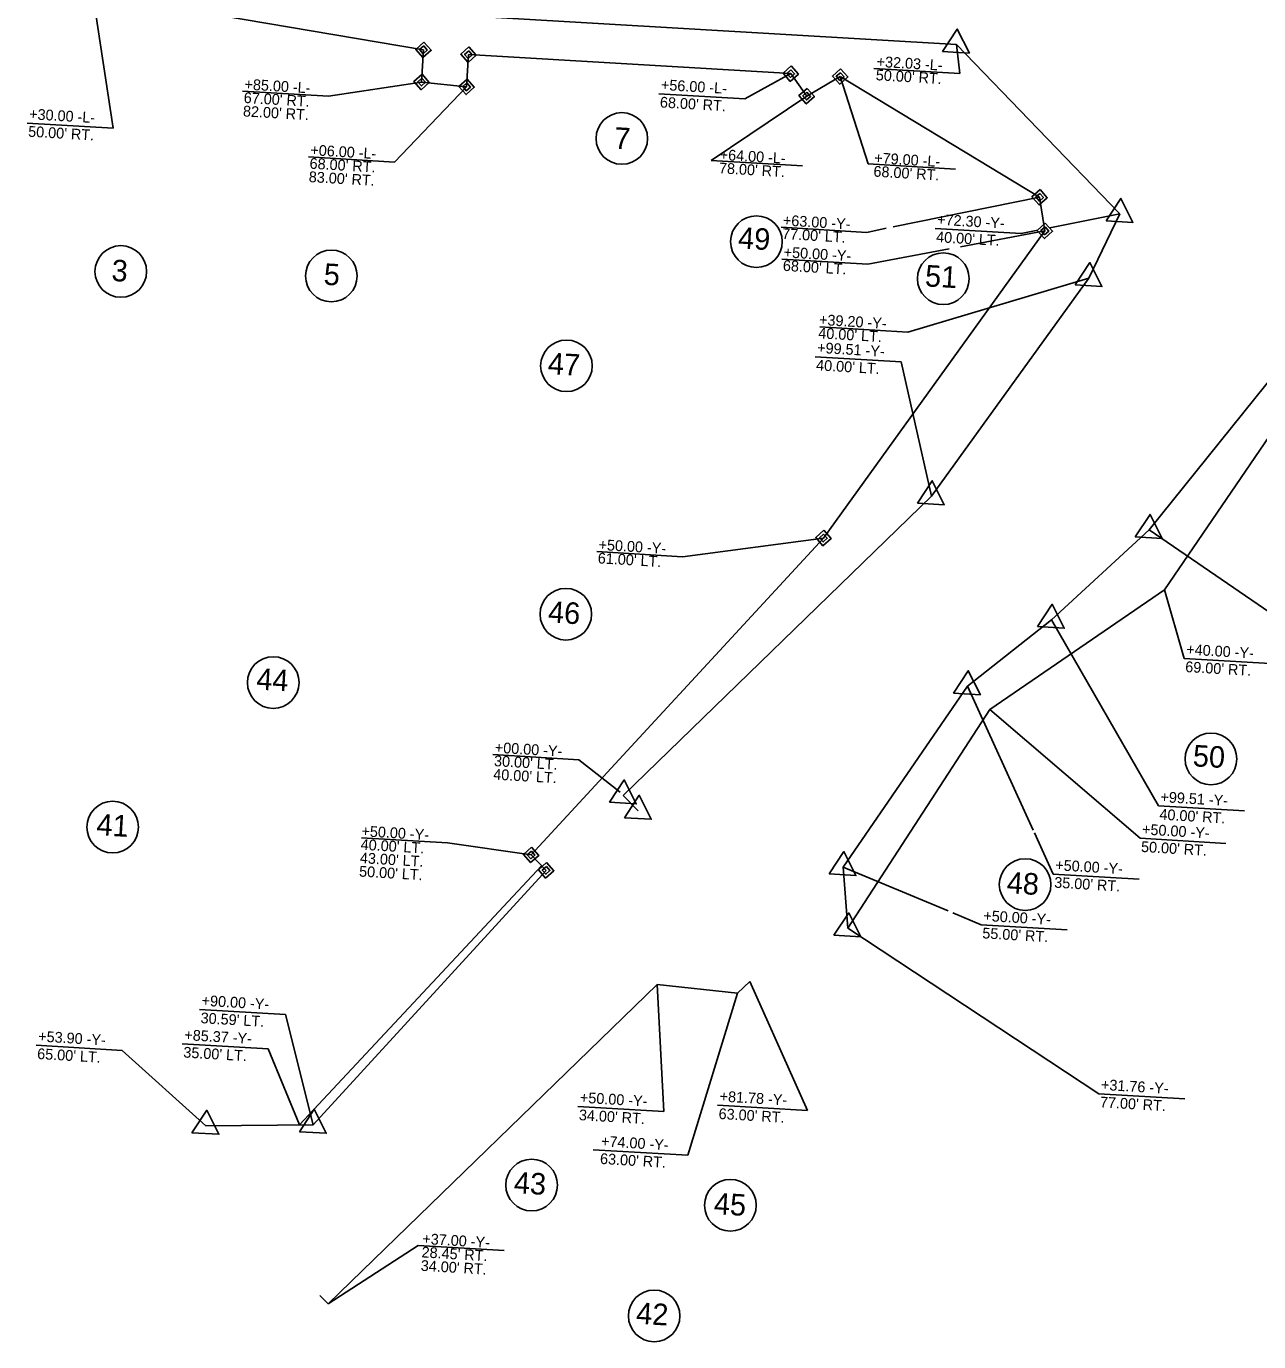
# Model space of a CAD drawing. Extents: x 2010883 to 2014849, y 442000 to 447413.
# Drawn here: x 2011335 to 2011908, y 444349 to 444960 of the extents above; entities that cross this region are included whole.
import ezdxf

# ---------------------------------------------------------------- set-up
doc = ezdxf.new("R2010")
doc.units = 0
for name, color, linetype in [('Prop Easement Construction', 7, 'Continuous'), ('Prop Easement Construction Station Offsets', 7, 'Continuous'), ('Prop Easement Permanent Utility', 7, 'Continuous'), ('Prop Easement Permanent Utility Station Offsets', 7, 'Continuous'), ('Prop Parcel Number CELL', 7, 'Continuous'), ('Prop Parcel Number Text', 7, 'Continuous'), ('Prop ROW Marker CELL', 7, 'Continuous'), ('Prop ROW Permanent Easement CELL', 7, 'Continuous'), ('Prop ROW RW Lines', 7, 'Continuous'), ('Prop ROW Station Offsets', 7, 'Continuous')]:
    doc.layers.add(name, color=color, linetype=linetype)

msp = doc.modelspace()

# ---------------------------------------------------------------- linework, layer by layer
at = {"layer": 'Prop Easement Construction'}
for p, q in [((2011864.2, 444698.09), (2011941.73, 444811.57)), ((2011783.13, 444642.47), (2011864.2, 444698.09)), ((2011717.13, 444540.72), (2011783.13, 444642.47)), ((2011462.36, 444449.38), (2011574.87, 444569.83)), ((2011475.74, 444366.18), (2011628.53, 444514.6)), ((2011628.53, 444514.6), (2011665.95, 444510.52)), ((2011665.95, 444510.52), (2011671.53, 444515.94)), ((2011471.88, 444370.16), (2011475.74, 444366.18))]:
    msp.add_line(p, q, dxfattribs=at)
at = {"layer": 'Prop Easement Construction Station Offsets'}
for p, q in [((2011864.2, 444698.09), (2011873.43, 444666.16)), ((2011873.43, 444666.16), (2011913.36, 444663.81)), ((2011783.13, 444642.47), (2011852.89, 444582.57)), ((2011852.89, 444582.57), (2011892.82, 444580.21)), ((2011628.53, 444514.6), (2011631.66, 444455.57)), ((2011671.53, 444515.94), (2011698.34, 444456.03)), ((2011665.95, 444510.52), (2011642.78, 444435.25)), ((2011407.95, 444487.02), (2011447.88, 444484.67)), ((2011462.36, 444449.38), (2011447.88, 444484.67)), ((2011591.73, 444457.92), (2011631.66, 444455.57)), ((2011656.64, 444458.49), (2011698.34, 444456.03)), ((2011598.86, 444437.84), (2011642.78, 444435.25)), ((2011475.74, 444366.18), (2011517.47, 444393.31)), ((2011517.47, 444393.31), (2011557.4, 444390.95))]:
    msp.add_line(p, q, dxfattribs=at)
at = {"layer": 'Prop Easement Permanent Utility'}
for p, q in [((2011366.24, 444975.07), (2011519.97, 444948.98)), ((2011519.97, 444948.98), (2011519.09, 444934)), ((2011540, 444931.77), (2011540.88, 444946.74)), ((2011540.88, 444946.74), (2011690.62, 444937.92)), ((2011690.62, 444937.92), (2011698.02, 444927.46)), ((2011698.02, 444927.46), (2011713.58, 444936.56)), ((2011713.58, 444936.56), (2011806.21, 444880.48)), ((2011519.09, 444934), (2011540, 444931.77)), ((2011808.65, 444864.86), (2011806.21, 444880.48)), ((2011705.79, 444722.09), (2011808.65, 444864.86)), ((2011570, 444574.85), (2011705.79, 444722.09)), ((2011570, 444574.85), (2011576.96, 444567.67)), ((2011468.76, 444449.44), (2011576.96, 444567.67))]:
    msp.add_line(p, q, dxfattribs=at)
at = {"layer": 'Prop Easement Permanent Utility Station Offsets'}
for p, q in [((2011366.24, 444975.07), (2011375.79, 444912.6)), ((2011690.62, 444937.92), (2011669.3, 444926.19)), ((2011713.58, 444936.56), (2011726.53, 444895.97)), ((2011519.09, 444934), (2011475.89, 444927.37)), ((2011540, 444931.77), (2011506.48, 444896.84)), ((2011435.96, 444929.73), (2011475.89, 444927.37)), ((2011629.37, 444928.54), (2011669.3, 444926.19)), ((2011698.02, 444927.46), (2011653.65, 444897.55)), ((2011335.86, 444914.96), (2011375.79, 444912.6)), ((2011466.55, 444899.19), (2011506.48, 444896.84)), ((2011653.65, 444897.55), (2011696.14, 444895.05)), ((2011726.53, 444895.97), (2011767.15, 444893.57)), ((2011806.21, 444880.48), (2011738.26, 444866.77)), ((2011686.09, 444866.51), (2011726.02, 444864.16)), ((2011734.89, 444866.05), (2011726.02, 444864.16)), ((2011808.65, 444864.86), (2011769.47, 444857.48)), ((2011686.45, 444851.71), (2011726.38, 444849.35)), ((2011764.25, 444856.49), (2011726.38, 444849.35)), ((2011705.79, 444722.09), (2011640.38, 444713.41)), ((2011600.45, 444715.77), (2011640.38, 444713.41)), ((2011491.25, 444582.75), (2011531.18, 444580.4)), ((2011570, 444574.85), (2011531.18, 444580.4))]:
    msp.add_line(p, q, dxfattribs=at)
at = {"layer": 'Prop Parcel Number CELL'}
for p, q in [((2011612.14, 444907.78), (2011612.14, 444907.78)), ((2011674.67, 444859.84), (2011674.67, 444859.84)), ((2011379.37, 444845.97), (2011379.37, 444845.97)), ((2011477.17, 444843.89), (2011477.17, 444843.89)), ((2011761.49, 444842.61), (2011761.49, 444842.61)), ((2011586.42, 444802.12), (2011586.42, 444802.12)), ((2011586.12, 444686.71), (2011586.12, 444686.71)), ((2011450.18, 444654.94), (2011450.18, 444654.94)), ((2011885.84, 444619.45), (2011885.84, 444619.45)), ((2011375.58, 444587.76), (2011375.58, 444587.76)), ((2011799.52, 444561.06), (2011799.52, 444561.06)), ((2011570.23, 444421.41), (2011570.23, 444421.41)), ((2011662.57, 444412.03), (2011662.57, 444412.03)), ((2011627.16, 444360.62), (2011627.16, 444360.62))]:
    msp.add_line(p, q, dxfattribs=at)
for centre in [(2011612.14, 444907.78), (2011674.67, 444859.84), (2011379.37, 444845.97), (2011477.17, 444843.89), (2011761.49, 444842.61), (2011586.42, 444802.12), (2011586.12, 444686.71), (2011450.18, 444654.94), (2011885.84, 444619.45), (2011375.58, 444587.76), (2011799.52, 444561.06), (2011570.23, 444421.41), (2011662.57, 444412.03), (2011627.16, 444360.62)]:
    msp.add_circle(centre, 12, dxfattribs=at)
at = {"layer": 'Prop ROW Marker CELL'}
for p, q in [((2011519.97, 444948.98), (2011519.97, 444948.98)), ((2011767.58, 444951.41), (2011767.58, 444951.41)), ((2011540.88, 444946.74), (2011540.88, 444946.74)), ((2011690.62, 444937.92), (2011690.62, 444937.92)), ((2011713.58, 444936.56), (2011713.58, 444936.56)), ((2011519.09, 444934), (2011519.09, 444934)), ((2011540, 444931.77), (2011540, 444931.77)), ((2011698.02, 444927.46), (2011698.02, 444927.46)), ((2011806.21, 444880.48), (2011806.21, 444880.48)), ((2011843.57, 444872.74), (2011843.57, 444872.74)), ((2011808.65, 444864.86), (2011808.65, 444864.86)), ((2011829.15, 444842.94), (2011829.15, 444842.94)), ((2011755.94, 444741.53), (2011755.94, 444741.53)), ((2011857.11, 444725.89), (2011857.11, 444725.89)), ((2011705.79, 444722.09), (2011705.79, 444722.09)), ((2011811.68, 444684.14), (2011811.68, 444684.14)), ((2011772.68, 444653.23), (2011772.68, 444653.23)), ((2011612.83, 444602.51), (2011612.83, 444602.51)), ((2011619.8, 444595.34), (2011619.8, 444595.34)), ((2011570, 444574.85), (2011570, 444574.85)), ((2011576.96, 444567.67), (2011576.96, 444567.67)), ((2011714.89, 444569.21), (2011714.89, 444569.21)), ((2011717.13, 444540.72), (2011717.13, 444540.72)), ((2011418.88, 444448.97), (2011418.88, 444448.97)), ((2011468.76, 444449.44), (2011468.76, 444449.44))]:
    msp.add_line(p, q, dxfattribs=at)
for points in [[(2011761.13, 444948.19), (2011768, 444958.6), (2011773.61, 444947.45)], [(2011837.12, 444869.51), (2011843.99, 444879.93), (2011849.6, 444868.78)], [(2011822.7, 444839.72), (2011829.57, 444850.13), (2011835.18, 444838.98)], [(2011749.49, 444738.3), (2011756.36, 444748.72), (2011761.96, 444737.57)], [(2011850.66, 444722.66), (2011857.53, 444733.07), (2011863.14, 444721.92)], [(2011805.23, 444680.92), (2011812.1, 444691.33), (2011817.7, 444680.18)], [(2011766.23, 444650.01), (2011773.1, 444660.42), (2011778.71, 444649.27)], [(2011606.38, 444599.29), (2011613.25, 444609.7), (2011618.86, 444598.55)], [(2011613.34, 444592.11), (2011620.22, 444602.53), (2011625.82, 444591.38)], [(2011708.44, 444565.98), (2011715.31, 444576.4), (2011720.91, 444565.25)], [(2011710.68, 444537.49), (2011717.56, 444547.91), (2011723.16, 444536.76)], [(2011412.43, 444445.74), (2011419.31, 444456.16), (2011424.91, 444445.01)], [(2011462.31, 444446.21), (2011469.18, 444456.62), (2011474.79, 444445.48)]]:
    msp.add_lwpolyline(points, close=True, dxfattribs=at)
at = {"layer": 'Prop ROW Permanent Easement CELL'}
for points in [[(2011520.19, 444952.57), (2011523.57, 444948.77), (2011519.76, 444945.38), (2011516.38, 444949.19)], [(2011520.08, 444950.77), (2011521.77, 444948.87), (2011519.87, 444947.18), (2011518.18, 444949.08)], [(2011541.09, 444950.34), (2011544.47, 444946.53), (2011540.67, 444943.15), (2011537.29, 444946.96)], [(2011540.99, 444948.54), (2011542.68, 444946.64), (2011540.77, 444944.95), (2011539.08, 444946.85)], [(2011519.3, 444937.6), (2011522.69, 444933.79), (2011518.88, 444930.41), (2011515.5, 444934.22)], [(2011690.83, 444941.51), (2011694.21, 444937.7), (2011690.41, 444934.32), (2011687.03, 444938.13)], [(2011690.73, 444939.71), (2011692.42, 444937.81), (2011690.51, 444936.12), (2011688.82, 444938.02)], [(2011713.79, 444940.16), (2011717.17, 444936.35), (2011713.37, 444932.97), (2011709.99, 444936.78)], [(2011713.69, 444938.36), (2011715.38, 444936.46), (2011713.47, 444934.77), (2011711.78, 444936.67)], [(2011519.2, 444935.8), (2011520.89, 444933.9), (2011518.99, 444932.21), (2011517.3, 444934.11)], [(2011540.21, 444935.36), (2011543.59, 444931.56), (2011539.79, 444928.18), (2011536.4, 444931.98)], [(2011540.1, 444933.57), (2011541.79, 444931.66), (2011539.89, 444929.97), (2011538.2, 444931.88)], [(2011698.23, 444931.06), (2011701.61, 444927.25), (2011697.81, 444923.87), (2011694.42, 444927.68)], [(2011698.12, 444929.26), (2011699.81, 444927.36), (2011697.91, 444925.67), (2011696.22, 444927.57)], [(2011806.42, 444884.08), (2011809.81, 444880.27), (2011806, 444876.89), (2011802.62, 444880.69)], [(2011806.32, 444882.28), (2011808.01, 444880.38), (2011806.11, 444878.69), (2011804.41, 444880.59)], [(2011808.86, 444868.45), (2011812.24, 444864.65), (2011808.44, 444861.27), (2011805.06, 444865.07)], [(2011808.76, 444866.66), (2011810.45, 444864.76), (2011808.54, 444863.06), (2011806.85, 444864.97)], [(2011706, 444725.69), (2011709.38, 444721.88), (2011705.58, 444718.5), (2011702.2, 444722.3)], [(2011705.89, 444723.89), (2011707.59, 444721.99), (2011705.68, 444720.3), (2011703.99, 444722.2)], [(2011570.21, 444578.44), (2011573.59, 444574.64), (2011569.78, 444571.25), (2011566.4, 444575.06)], [(2011570.1, 444576.64), (2011571.79, 444574.74), (2011569.89, 444573.05), (2011568.2, 444574.95)], [(2011577.18, 444571.27), (2011580.56, 444567.46), (2011576.75, 444564.08), (2011573.37, 444567.89)], [(2011577.07, 444569.47), (2011578.76, 444567.57), (2011576.86, 444565.88), (2011575.17, 444567.78)]]:
    msp.add_lwpolyline(points, close=True, dxfattribs=at)
at = {"layer": 'Prop ROW RW Lines'}
for p, q in [((2011335.47, 444976.88), (2011767.58, 444951.41)), ((2011767.58, 444951.41), (2011843.57, 444872.74)), ((2011829.15, 444842.94), (2011843.57, 444872.74)), ((2011755.94, 444741.53), (2011829.15, 444842.94)), ((2011857.11, 444725.89), (2011917.02, 444800.42)), ((2011612.83, 444602.51), (2011755.94, 444741.53)), ((2011811.68, 444684.14), (2011857.11, 444725.89)), ((2011772.68, 444653.23), (2011811.68, 444684.14)), ((2011714.89, 444569.21), (2011772.68, 444653.23)), ((2011612.83, 444602.51), (2011619.8, 444595.34)), ((2011717.13, 444540.72), (2011714.89, 444569.21)), ((2011418.88, 444448.97), (2011468.76, 444449.44))]:
    msp.add_line(p, q, dxfattribs=at)
at = {"layer": 'Prop ROW Station Offsets'}
for p, q in [((2011767.58, 444951.41), (2011769.1, 444937.95)), ((2011729.17, 444940.3), (2011769.1, 444937.95)), ((2011843.57, 444872.74), (2011811.02, 444866.26)), ((2011757.7, 444865.94), (2011797.63, 444863.59)), ((2011805.42, 444865.14), (2011797.63, 444863.59)), ((2011829.15, 444842.94), (2011745, 444817.84)), ((2011704.06, 444820.25), (2011745, 444817.84)), ((2011701.95, 444806.38), (2011741.88, 444804.02)), ((2011755.94, 444741.53), (2011741.88, 444804.02)), ((2011921.57, 444681.71), (2011857.11, 444725.89)), ((2011861.44, 444597.6), (2011811.68, 444684.14)), ((2011803.28, 444586.28), (2011772.68, 444653.23)), ((2011552.24, 444621.43), (2011592.17, 444619.08)), ((2011611.43, 444603.95), (2011592.17, 444619.08)), ((2011861.44, 444597.6), (2011901.37, 444595.25)), ((2011812.57, 444565.95), (2011803.85, 444585.03)), ((2011763.77, 444548.82), (2011714.89, 444569.21)), ((2011812.57, 444565.95), (2011852.5, 444563.6)), ((2011779.15, 444542.4), (2011765.97, 444547.9)), ((2011833.8, 444463.87), (2011717.13, 444540.72)), ((2011779.15, 444542.4), (2011819.08, 444540.05)), ((2011415.98, 444502.99), (2011455.91, 444500.63)), ((2011468.76, 444449.44), (2011455.91, 444500.63)), ((2011340.06, 444486.35), (2011379.99, 444483.99)), ((2011418.88, 444448.97), (2011379.99, 444483.99)), ((2011833.8, 444463.87), (2011873.73, 444461.52))]:
    msp.add_line(p, q, dxfattribs=at)

# ---------------------------------------------------------------- texts
at = {"layer": 'Prop Easement Construction Station Offsets'}
for s, p in [('+40.00 -Y-', (2011874.26, 444667.95)), ("69.00' RT.", (2011873.79, 444659.84)), ('+50.00 -Y-', (2011853.72, 444584.35)), ("50.00' RT.", (2011853.24, 444576.24)), ('+85.37 -Y-', (2011408.78, 444488.81)), ("35.00' LT.", (2011408.31, 444480.7)), ('+50.00 -Y-', (2011592.56, 444459.7)), ('+81.78 -Y-', (2011657.47, 444460.27)), ("34.00' RT.", (2011592.09, 444451.59)), ("63.00' RT.", (2011656.99, 444452.16)), ('+74.00 -Y-', (2011602.38, 444439.38)), ("63.00' RT.", (2011601.9, 444431.27)), ('+37.00 -Y-', (2011519.35, 444394.06)), ("28.45' RT.", (2011518.99, 444387.82)), ("34.00' RT.", (2011518.62, 444381.58))]:
    msp.add_text(s, height=5, rotation=356.62643, dxfattribs=at).set_placement(p)
at = {"layer": 'Prop Easement Permanent Utility Station Offsets'}
for s, p in [('+85.00 -L-', (2011436.73, 444930.56)), ('+56.00 -L-', (2011630.2, 444930.33)), ("67.00' RT.", (2011436.37, 444924.32)), ("68.00' RT.", (2011629.73, 444922.21)), ('+30.00 -L-', (2011336.69, 444916.74)), ("82.00' RT.", (2011436, 444918.08)), ("50.00' RT.", (2011336.22, 444908.63)), ('+06.00 -L-', (2011467.33, 444900.02)), ('+64.00 -L-', (2011657.52, 444897.85)), ('+79.00 -L-', (2011729.3, 444896.33)), ("68.00' RT.", (2011466.96, 444893.78)), ("78.00' RT.", (2011657.15, 444891.61)), ("68.00' RT.", (2011728.93, 444890.09)), ("83.00' RT.", (2011466.59, 444887.54)), ('+63.00 -Y-', (2011686.86, 444867.34)), ("77.00' LT.", (2011686.49, 444861.1)), ('+50.00 -Y-', (2011687.23, 444852.54)), ("68.00' LT.", (2011686.86, 444846.3)), ('+50.00 -Y-', (2011601.22, 444716.6)), ("61.00' LT.", (2011600.86, 444710.36)), ('+50.00 -Y-', (2011491.07, 444583.51)), ("40.00' LT.", (2011490.71, 444577.27)), ("43.00' LT.", (2011490.34, 444571.03)), ("50.00' LT.", (2011489.97, 444564.79))]:
    msp.add_text(s, height=5, rotation=356.62643, dxfattribs=at).set_placement(p)
at = {"layer": 'Prop Parcel Number Text'}
for s, p in [('7', (2011608.38, 444903.08)), ('49', (2011665.95, 444856.71)), ('3', (2011374.87, 444841.6)), ('5', (2011473.44, 444839.83)), ('51', (2011752.8, 444839.09)), ('47', (2011577.58, 444798.34)), ('46', (2011577.67, 444682.87)), ('44', (2011442.15, 444651.7)), ('50', (2011877.23, 444616.05)), ('41', (2011367.88, 444584.06)), ('48', (2011790.78, 444557.06)), ('43', (2011561.8, 444417.68)), ('45', (2011654.72, 444407.93)), ('42', (2011618.6, 444356.98))]:
    msp.add_text(s, height=10, rotation=356.62643, dxfattribs=at).set_placement(p)
at = {"layer": 'Prop ROW Station Offsets'}
for s, p in [('+32.03 -L-', (2011730.4, 444941.11)), ("50.00' RT.", (2011730.03, 444934.87)), ('+72.30 -Y-', (2011758.53, 444867.72)), ("40.00' LT.", (2011758.05, 444859.61)), ('+39.20 -Y-', (2011703.67, 444821.16)), ("40.00' LT.", (2011703.31, 444814.92)), ('+99.51 -Y-', (2011702.78, 444808.16)), ("40.00' LT.", (2011702.3, 444800.05)), ('+00.00 -Y-', (2011553.02, 444622.35)), ("30.00' LT.", (2011552.65, 444616.11)), ("40.00' LT.", (2011552.29, 444609.88)), ('+99.51 -Y-', (2011862.27, 444599.39)), ("40.00' RT.", (2011861.79, 444591.28)), ('+50.00 -Y-', (2011813.4, 444567.74)), ("35.00' RT.", (2011812.92, 444559.63)), ('+50.00 -Y-', (2011779.98, 444544.19)), ("55.00' RT.", (2011779.5, 444536.08)), ('+90.00 -Y-', (2011416.81, 444504.77)), ("30.59' LT.", (2011416.34, 444496.66)), ('+53.90 -Y-', (2011340.89, 444488.13)), ("65.00' LT.", (2011340.41, 444480.02)), ('+31.76 -Y-', (2011834.64, 444465.66)), ("77.00' RT.", (2011834.16, 444457.55))]:
    msp.add_text(s, height=5, rotation=356.62643, dxfattribs=at).set_placement(p)

doc.saveas('drawing.dxf')
